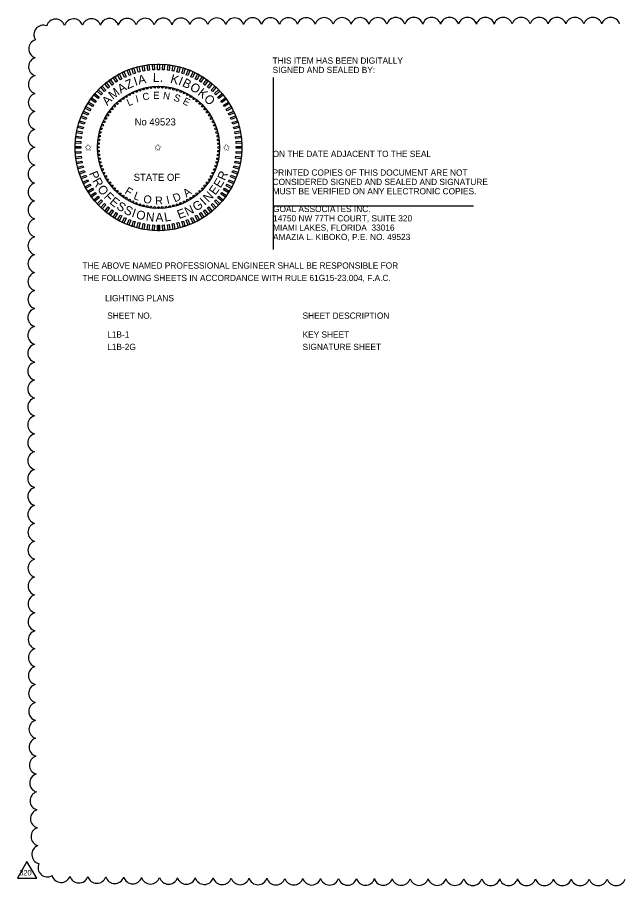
# Model space of a CAD drawing. Extents: x -811.2 to -755.6, y -2295.2 to -2235.1.
# Drawn here: x -783.8 to -777.02, y -2269.67 to -2259.9 of the extents above; entities that cross this region are included whole.
import ezdxf

# ---------------------------------------------------------------- set-up
doc = ezdxf.new("R2010")
doc.units = 0
for name, color, linetype in [('Cloud_dp', 7, 'Continuous'), ('Logo_dp', 7, 'Continuous'), ('NonPlottingEle_dp', 7, 'Continuous'), ('ScratchEle_dp', 7, 'Continuous'), ('TextMisc', 7, 'Continuous'), ('TextNotes', 7, 'Continuous')]:
    doc.layers.add(name, color=color, linetype=linetype)

msp = doc.modelspace()

# ---------------------------------------------------------------- linework, layer by layer
at = {"layer": 'Cloud_dp'}
msp.add_lwpolyline([(-783.6889, -2269.3954), (-783.7966, -2269.5835), (-783.576, -2269.5835)], close=True, dxfattribs=at)
for centre, start, end in [((-782.5594, -2260.0139), 17.87787, 162.87787), ((-782.3579, -2260.0127), 17.82689, 162.82689), ((-782.1564, -2260.0116), 17.78716, 162.78716), ((-781.9548, -2260.0107), 17.75505, 162.75505), ((-781.7533, -2260.0098), 17.72841, 162.72841), ((-781.5518, -2260.009), 17.70584, 162.70584), ((-781.3502, -2260.0084), 17.6864, 162.6864), ((-781.1487, -2260.0077), 17.66942, 162.66942), ((-780.9472, -2260.0072), 17.65443, 162.65443), ((-780.7456, -2260.0066), 17.64106, 162.64106), ((-780.5441, -2260.0062), 17.62905, 162.62905), ((-780.3425, -2260.0057), 17.61817, 162.61817), ((-780.141, -2260.0053), 17.60826, 162.60826), ((-779.9394, -2260.005), 17.59919, 162.59919), ((-779.7379, -2260.0046), 17.59084, 162.59084), ((-779.5364, -2260.0043), 17.58312, 162.58312), ((-779.3348, -2260.004), 17.57595, 162.57595), ((-779.1333, -2260.0038), 17.56928, 162.56928), ((-778.9317, -2260.0036), 17.56305, 162.56305), ((-778.7302, -2260.0033), 17.55721, 162.55721), ((-778.5286, -2260.0032), 17.55172, 162.55172), ((-778.3271, -2260.003), 17.54655, 162.54655), ((-778.1255, -2260.0028), 17.54167, 162.54167), ((-777.924, -2260.0027), 17.53705, 162.53705), ((-777.7224, -2260.0026), 17.53267, 162.53267), ((-777.5209, -2260.0025), 17.52851, 162.52851), ((-777.3194, -2260.0024), 17.52455, 162.52455), ((-777.1178, -2260.0023), 17.52079, 162.52079), ((-783.5053, -2260.0909), 68.43954, 213.43954), ((-783.3652, -2260.0225), 18.59454, 163.59454), ((-783.1638, -2260.0193), 18.21421, 163.21421), ((-782.9624, -2260.0171), 18.04696, 163.04696), ((-782.7609, -2260.0154), 17.94666, 162.94666), ((-783.563, -2260.2503), 106.80445, 251.80445), ((-783.565, -2260.4517), 107.04367, 252.04367), ((-783.5664, -2260.6532), 107.15618, 252.15618), ((-783.5675, -2260.8547), 107.22533, 252.22533), ((-783.5684, -2261.0562), 107.27338, 252.27338), ((-783.5691, -2261.2578), 107.30928, 252.30928), ((-783.5697, -2261.4593), 107.33743, 252.33743), ((-783.5703, -2261.6608), 107.36027, 252.36027), ((-783.5707, -2261.8624), 107.37928, 252.37928), ((-783.5711, -2262.0639), 107.39543, 252.39543), ((-783.5715, -2262.2655), 107.40937, 252.40937), ((-783.5717, -2262.467), 107.42156, 252.42156), ((-783.572, -2262.6685), 107.43234, 252.43234), ((-783.5722, -2262.8701), 107.44197, 252.44197), ((-783.5724, -2263.0716), 107.45063, 252.45063), ((-783.5726, -2263.2732), 107.45847, 252.45847), ((-783.5727, -2263.4747), 107.46563, 252.46563), ((-783.5728, -2263.6763), 107.47218, 252.47218), ((-783.5729, -2263.8778), 107.47822, 252.47822), ((-783.573, -2264.0794), 107.4838, 252.4838), ((-783.573, -2264.2809), 107.48899, 252.48899), ((-783.5731, -2264.4824), 107.49382, 252.49382), ((-783.5731, -2264.684), 107.49843, 252.49843), ((-783.573, -2264.8855), 107.51148, 252.51148), ((-783.573, -2265.0871), 107.53101, 252.53101), ((-783.5728, -2265.2886), 107.55191, 252.55191), ((-783.5726, -2265.4901), 107.57435, 252.57435), ((-783.5723, -2265.6917), 107.59852, 252.59852), ((-783.5719, -2265.8932), 107.62468, 252.62468), ((-783.5714, -2266.0947), 107.65309, 252.65309), ((-783.5708, -2266.2963), 107.68411, 252.68411), ((-783.5701, -2266.4978), 107.71817, 252.71817), ((-783.5693, -2266.6993), 107.75578, 252.75578), ((-783.5683, -2266.9009), 107.79762, 252.79762), ((-783.5672, -2267.1024), 107.84454, 252.84454), ((-783.5659, -2267.3039), 107.89767, 252.89767), ((-783.5644, -2267.5054), 107.95851, 252.95851), ((-783.5626, -2267.7069), 108.02912, 253.02912), ((-783.5606, -2267.9084), 108.11243, 253.11243), ((-783.5583, -2268.1099), 108.21279, 253.21279), ((-783.5556, -2268.3113), 108.33694, 253.33694), ((-783.5523, -2268.5128), 108.49611, 253.49611), ((-783.5485, -2268.7142), 108.71068, 253.71068), ((-783.5437, -2268.9155), 109.02298, 254.02298), ((-783.5374, -2269.1166), 109.54201, 254.54201), ((-783.5282, -2269.3173), 110.71007, 255.71007), ((-783.4585, -2269.4643), 155.06518, 300.06518), ((-783.3038, -2269.5272), 195.62937, 340.62937), ((-783.1027, -2269.5327), 196.26473, 341.26473), ((-782.9013, -2269.5365), 196.54985, 341.54985), ((-782.6999, -2269.5396), 196.72204, 341.72204), ((-782.4984, -2269.5421), 196.84059, 341.84059), ((-782.2969, -2269.5443), 196.92865, 341.92865), ((-782.0954, -2269.5461), 196.99739, 341.99739), ((-781.8939, -2269.5478), 197.053, 342.053), ((-781.6924, -2269.5493), 197.09919, 342.09919), ((-781.4909, -2269.5506), 197.13834, 342.13834), ((-781.2893, -2269.5519), 197.17209, 342.17209), ((-781.0878, -2269.553), 197.20158, 342.20158), ((-780.8863, -2269.554), 197.22762, 342.22762), ((-780.6847, -2269.5549), 197.25085, 342.25085), ((-780.4832, -2269.5557), 197.27174, 342.27174), ((-780.2817, -2269.5565), 197.29065, 342.29065), ((-780.0801, -2269.5572), 197.30788, 342.30788), ((-779.8786, -2269.5578), 197.32367, 342.32367), ((-779.6771, -2269.5584), 197.3382, 342.3382), ((-779.4755, -2269.559), 197.35163, 342.35163), ((-779.274, -2269.5595), 197.3641, 342.3641), ((-779.0724, -2269.5599), 197.37571, 342.37571), ((-778.8709, -2269.5604), 197.38657, 342.38657), ((-778.6693, -2269.5607), 197.39674, 342.39674), ((-778.4678, -2269.5611), 197.40629, 342.40629), ((-778.2663, -2269.5614), 197.4153, 342.4153), ((-778.0647, -2269.5617), 197.4238, 342.4238), ((-777.8632, -2269.5619), 197.43184, 342.43184), ((-777.6616, -2269.5622), 197.43947, 342.43947), ((-777.4601, -2269.5624), 197.44671, 342.44671), ((-777.2585, -2269.5625), 197.4536, 342.4536), ((-777.057, -2269.5627), 197.46017, 342.46017)]:
    msp.add_arc(centre, 0.1057, start, end, dxfattribs=at)
at = {"layer": 'Logo_dp'}
for p, q in [((-782.2178, -2262.2978), (-782.218, -2262.2353)), ((-782.2078, -2262.2978), (-782.208, -2262.2353)), ((-782.1978, -2262.2978), (-782.198, -2262.2353))]:
    msp.add_line(p, q, dxfattribs=at)
for points in [[(-782.5205, -2260.543), (-782.5392, -2260.5504), (-782.5622, -2260.4923), (-782.5434, -2260.4849)], [(-782.4685, -2260.525), (-782.4877, -2260.5312), (-782.507, -2260.4718), (-782.4878, -2260.4656)], [(-782.4156, -2260.5102), (-782.4351, -2260.5152), (-782.4506, -2260.4548), (-782.4311, -2260.4498)], [(-782.3618, -2260.4989), (-782.3816, -2260.5026), (-782.3933, -2260.4413), (-782.3735, -2260.4375)], [(-782.3074, -2260.4909), (-782.3274, -2260.4934), (-782.3352, -2260.4315), (-782.3152, -2260.4289)], [(-782.2526, -2260.4864), (-782.2727, -2260.4876), (-782.2767, -2260.4253), (-782.2565, -2260.424)], [(-782.1976, -2260.4853), (-782.2178, -2260.4853), (-782.2178, -2260.4228), (-782.1976, -2260.4228)], [(-782.1427, -2260.4876), (-782.1629, -2260.4864), (-782.1589, -2260.4241), (-782.1388, -2260.4253)], [(-782.088, -2260.4934), (-782.1081, -2260.4909), (-782.1002, -2260.429), (-782.0802, -2260.4315)], [(-782.0338, -2260.5027), (-782.0537, -2260.4989), (-782.042, -2260.4376), (-782.0221, -2260.4413)], [(-781.9803, -2260.5153), (-781.9999, -2260.5103), (-781.9844, -2260.4498), (-781.9648, -2260.4548)], [(-781.9277, -2260.5312), (-781.9469, -2260.525), (-781.9276, -2260.4656), (-781.9084, -2260.4719)], [(-781.8762, -2260.5505), (-781.895, -2260.543), (-781.872, -2260.485), (-781.8532, -2260.4924)], [(-782.6681, -2260.616), (-782.6851, -2260.6268), (-782.7186, -2260.5741), (-782.7015, -2260.5633)], [(-782.6204, -2260.5886), (-782.6381, -2260.5983), (-782.6682, -2260.5436), (-782.6505, -2260.5339)], [(-782.5712, -2260.5642), (-782.5894, -2260.5728), (-782.616, -2260.5163), (-782.5978, -2260.5077)], [(-781.826, -2260.5729), (-781.8443, -2260.5643), (-781.8177, -2260.5078), (-781.7994, -2260.5164)], [(-781.7773, -2260.5984), (-781.795, -2260.5887), (-781.7649, -2260.534), (-781.7473, -2260.5437)], [(-781.7303, -2260.6269), (-781.7474, -2260.6161), (-781.7139, -2260.5634), (-781.6969, -2260.5742)], [(-782.7994, -2260.7155), (-782.8141, -2260.7293), (-782.8568, -2260.6838), (-782.8421, -2260.6699)], [(-782.7577, -2260.6796), (-782.7733, -2260.6925), (-782.8131, -2260.6443), (-782.7975, -2260.6315)], [(-782.7139, -2260.6464), (-782.7302, -2260.6583), (-782.7669, -2260.6078), (-782.7506, -2260.5959)], [(-781.6852, -2260.6584), (-781.7016, -2260.6465), (-781.6649, -2260.596), (-781.6485, -2260.6079)], [(-781.6422, -2260.6926), (-781.6578, -2260.6797), (-781.618, -2260.6316), (-781.6024, -2260.6445)], [(-781.6014, -2260.7294), (-781.6161, -2260.7156), (-781.5734, -2260.6701), (-781.5586, -2260.6839)], [(-782.8755, -2260.7947), (-782.8884, -2260.8102), (-782.9365, -2260.7704), (-782.9237, -2260.7549)], [(-782.8387, -2260.7539), (-782.8525, -2260.7686), (-782.898, -2260.7258), (-782.8842, -2260.7111)], [(-781.563, -2260.7687), (-781.5768, -2260.754), (-781.5313, -2260.7113), (-781.5175, -2260.726)], [(-781.5271, -2260.8104), (-781.54, -2260.7948), (-781.4919, -2260.755), (-781.479, -2260.7706)], [(-782.9412, -2260.8828), (-782.952, -2260.8999), (-783.0047, -2260.8664), (-782.9939, -2260.8494)], [(-782.9097, -2260.8377), (-782.9216, -2260.8541), (-782.9721, -2260.8174), (-782.9603, -2260.801)], [(-781.4939, -2260.8542), (-781.5058, -2260.8379), (-781.4553, -2260.8012), (-781.4434, -2260.8175)], [(-781.4635, -2260.9), (-781.4744, -2260.883), (-781.4216, -2260.8495), (-781.4108, -2260.8666)], [(-782.9952, -2260.9785), (-783.0038, -2260.9968), (-783.0603, -2260.9702), (-783.0517, -2260.9519)], [(-782.9697, -2260.9298), (-782.9794, -2260.9475), (-783.0341, -2260.9174), (-783.0244, -2260.8997)], [(-781.4361, -2260.9477), (-781.4458, -2260.93), (-781.3911, -2260.8999), (-781.3814, -2260.9176)], [(-781.4117, -2260.9969), (-781.4203, -2260.9787), (-781.3638, -2260.9521), (-781.3552, -2260.9704)], [(-783.0369, -2261.0802), (-783.0431, -2261.0994), (-783.1025, -2261.0801), (-783.0963, -2261.0609)], [(-783.0176, -2261.0287), (-783.0251, -2261.0475), (-783.0831, -2261.0245), (-783.0757, -2261.0057)], [(-781.3905, -2261.0477), (-781.3979, -2261.0289), (-781.3399, -2261.0059), (-781.3324, -2261.0247)], [(-781.3725, -2261.0996), (-781.3787, -2261.0804), (-781.3193, -2261.0611), (-781.3131, -2261.0803)], [(-783.0654, -2261.1863), (-783.0692, -2261.2062), (-783.1306, -2261.1945), (-783.1268, -2261.1746)], [(-783.0528, -2261.1328), (-783.0578, -2261.1524), (-783.1183, -2261.1368), (-783.1133, -2261.1173)], [(-781.3577, -2261.1526), (-781.3628, -2261.133), (-781.3023, -2261.1175), (-781.2973, -2261.137)], [(-781.3464, -2261.2063), (-781.3502, -2261.1865), (-781.2888, -2261.1748), (-781.285, -2261.1946)], [(-783.0747, -2261.2405), (-783.0772, -2261.2606), (-783.1391, -2261.2527), (-783.1366, -2261.2327)], [(-781.3384, -2261.2607), (-781.3409, -2261.2407), (-781.279, -2261.2329), (-781.2765, -2261.2529)], [(-783.0828, -2261.3501), (-783.0828, -2261.3703), (-783.1453, -2261.3703), (-783.1453, -2261.3501)], [(-783.0805, -2261.2952), (-783.0817, -2261.3153), (-783.1441, -2261.3114), (-783.1428, -2261.2913)], [(-781.3339, -2261.3155), (-781.3351, -2261.2954), (-781.2728, -2261.2915), (-781.2716, -2261.3116)], [(-781.3328, -2261.3705), (-781.3328, -2261.3503), (-781.2703, -2261.3503), (-781.2703, -2261.3705)], [(-783.0818, -2261.4051), (-783.0805, -2261.4252), (-783.1428, -2261.4291), (-783.1441, -2261.409)], [(-783.0772, -2261.4599), (-783.0747, -2261.4799), (-783.1366, -2261.4877), (-783.1392, -2261.4677)], [(-781.341, -2261.4801), (-781.3384, -2261.4601), (-781.2765, -2261.4679), (-781.279, -2261.4879)], [(-781.3351, -2261.4254), (-781.3339, -2261.4053), (-781.2716, -2261.4092), (-781.2728, -2261.4293)], [(-783.0693, -2261.5143), (-783.0655, -2261.5341), (-783.1268, -2261.5458), (-783.1306, -2261.526)], [(-783.0579, -2261.568), (-783.0529, -2261.5876), (-783.1133, -2261.6031), (-783.1184, -2261.5836)], [(-781.3628, -2261.5878), (-781.3578, -2261.5682), (-781.2973, -2261.5838), (-781.3023, -2261.6033)], [(-781.3502, -2261.5343), (-781.3464, -2261.5144), (-781.2851, -2261.5261), (-781.2889, -2261.546)], [(-783.0432, -2261.621), (-783.0369, -2261.6402), (-783.0963, -2261.6595), (-783.1025, -2261.6403)], [(-781.3788, -2261.6404), (-781.3725, -2261.6212), (-781.3131, -2261.6405), (-781.3194, -2261.6597)], [(-783.0251, -2261.673), (-783.0177, -2261.6917), (-783.0758, -2261.7147), (-783.0832, -2261.6959)], [(-783.0039, -2261.7237), (-782.9953, -2261.7419), (-783.0518, -2261.7685), (-783.0604, -2261.7502)], [(-781.4204, -2261.7421), (-781.4118, -2261.7238), (-781.3553, -2261.7504), (-781.3639, -2261.7687)], [(-781.398, -2261.6919), (-781.3906, -2261.6731), (-781.3325, -2261.6961), (-781.3399, -2261.7149)], [(-782.9795, -2261.7729), (-782.9698, -2261.7906), (-783.0245, -2261.8207), (-783.0342, -2261.803)], [(-782.9521, -2261.8206), (-782.9413, -2261.8376), (-782.994, -2261.8711), (-783.0048, -2261.854)], [(-781.4745, -2261.8378), (-781.4636, -2261.8207), (-781.4109, -2261.8542), (-781.4217, -2261.8712)], [(-781.4459, -2261.7908), (-781.4362, -2261.7731), (-781.3815, -2261.8032), (-781.3912, -2261.8209)], [(-782.9217, -2261.8664), (-782.9099, -2261.8827), (-782.9604, -2261.9194), (-782.9722, -2261.9031)], [(-782.8885, -2261.9102), (-782.8757, -2261.9258), (-782.9238, -2261.9656), (-782.9366, -2261.95)], [(-782.8527, -2261.9519), (-782.8388, -2261.9666), (-782.8844, -2262.0093), (-782.8982, -2261.9946)], [(-781.5769, -2261.9667), (-781.5631, -2261.952), (-781.5176, -2261.9948), (-781.5314, -2262.0095)], [(-781.5401, -2261.9259), (-781.5272, -2261.9104), (-781.4791, -2261.9502), (-781.492, -2261.9657)], [(-781.5059, -2261.8829), (-781.494, -2261.8665), (-781.4435, -2261.9032), (-781.4554, -2261.9196)], [(-782.8142, -2261.9912), (-782.7995, -2262.005), (-782.8423, -2262.0505), (-782.857, -2262.0367)], [(-782.7734, -2262.028), (-782.7579, -2262.0409), (-782.7977, -2262.089), (-782.8132, -2262.0761)], [(-781.6579, -2262.041), (-781.6423, -2262.0281), (-781.6025, -2262.0763), (-781.6181, -2262.0891)], [(-781.6162, -2262.0051), (-781.6015, -2261.9913), (-781.5588, -2262.0368), (-781.5735, -2262.0507)], [(-782.7304, -2262.0622), (-782.7141, -2262.0741), (-782.7508, -2262.1246), (-782.7671, -2262.1127)], [(-782.6853, -2262.0937), (-782.6682, -2262.1045), (-782.7017, -2262.1572), (-782.7187, -2262.1464)], [(-782.6383, -2262.1222), (-782.6206, -2262.1319), (-782.6507, -2262.1866), (-782.6684, -2262.1769)], [(-782.5896, -2262.1477), (-782.5713, -2262.1563), (-782.5979, -2262.2128), (-782.6162, -2262.2042)], [(-781.8445, -2262.1564), (-781.8262, -2262.1478), (-781.7996, -2262.2043), (-781.8179, -2262.2129)], [(-781.7952, -2262.132), (-781.7775, -2262.1223), (-781.7474, -2262.177), (-781.7651, -2262.1867)], [(-781.7475, -2262.1046), (-781.7305, -2262.0938), (-781.697, -2262.1465), (-781.7141, -2262.1573)], [(-781.7017, -2262.0742), (-781.6854, -2262.0623), (-781.6487, -2262.1129), (-781.665, -2262.1247)], [(-782.5394, -2262.1701), (-782.5206, -2262.1776), (-782.5436, -2262.2356), (-782.5624, -2262.2282)], [(-782.4879, -2262.1894), (-782.4687, -2262.1956), (-782.488, -2262.255), (-782.5072, -2262.2487)], [(-782.4353, -2262.2053), (-782.4157, -2262.2103), (-782.4313, -2262.2708), (-782.4508, -2262.2658)], [(-782.3818, -2262.2179), (-782.362, -2262.2217), (-782.3737, -2262.283), (-782.3935, -2262.2793)], [(-782.3276, -2262.2272), (-782.3076, -2262.2297), (-782.3154, -2262.2916), (-782.3354, -2262.2891)], [(-782.2729, -2262.233), (-782.2528, -2262.2342), (-782.2567, -2262.2966), (-782.2768, -2262.2953)], [(-782.218, -2262.2353), (-782.1978, -2262.2353), (-782.1978, -2262.2978), (-782.218, -2262.2978)], [(-782.163, -2262.2342), (-782.1429, -2262.233), (-782.139, -2262.2953), (-782.1591, -2262.2966)], [(-782.1082, -2262.2297), (-782.0882, -2262.2272), (-782.0804, -2262.2891), (-782.1004, -2262.2917)], [(-782.0539, -2262.2217), (-782.034, -2262.218), (-782.0223, -2262.2793), (-782.0422, -2262.2831)], [(-782.0001, -2262.2104), (-781.9805, -2262.2054), (-781.965, -2262.2658), (-781.9845, -2262.2709)], [(-781.9471, -2262.1957), (-781.9279, -2262.1894), (-781.9086, -2262.2488), (-781.9278, -2262.255)], [(-781.8952, -2262.1776), (-781.8764, -2262.1702), (-781.8534, -2262.2283), (-781.8722, -2262.2357)]]:
    msp.add_lwpolyline(points, close=True, dxfattribs=at)
for centre in [(-782.3342, -2260.6947), (-782.2922, -2260.6881), (-782.2498, -2260.6841), (-782.2072, -2260.6828), (-782.1647, -2260.6842), (-782.1223, -2260.6882), (-782.0803, -2260.6949), (-782.5703, -2260.788), (-782.5337, -2260.7664), (-782.4958, -2260.7471), (-782.4567, -2260.7302), (-782.4166, -2260.7158), (-782.3757, -2260.704), (-782.0388, -2260.7043), (-781.9979, -2260.7162), (-781.9579, -2260.7306), (-781.9189, -2260.7476), (-781.8809, -2260.7669), (-781.8443, -2260.7886), (-782.7013, -2260.8961), (-782.6712, -2260.8661), (-782.6392, -2260.8379), (-782.6056, -2260.8119), (-781.8092, -2260.8125), (-781.7755, -2260.8387), (-781.7436, -2260.8668), (-782.7556, -2260.9616), (-782.7295, -2260.928), (-781.7136, -2260.897), (-781.6855, -2260.9289), (-781.6594, -2260.9626), (-782.8206, -2261.0713), (-782.8012, -2261.0334), (-782.7795, -2260.9968), (-781.6355, -2260.9978), (-781.6139, -2261.0344), (-781.5946, -2261.0724), (-782.852, -2261.1504), (-782.8375, -2261.1104), (-781.5777, -2261.1114), (-781.5633, -2261.1515), (-782.8799, -2261.2748), (-782.8732, -2261.2328), (-782.8639, -2261.1913), (-781.5515, -2261.1924), (-781.5422, -2261.2339), (-781.5356, -2261.276), (-782.8853, -2261.3597), (-782.8839, -2261.3172), (-781.5316, -2261.3183), (-781.5303, -2261.3609), (-782.884, -2261.4023), (-782.88, -2261.4447), (-781.5358, -2261.4458), (-781.5317, -2261.4034), (-782.8734, -2261.4867), (-782.8641, -2261.5282), (-782.8523, -2261.5691), (-781.5637, -2261.5702), (-781.5518, -2261.5293), (-781.5425, -2261.4878), (-782.8379, -2261.6092), (-782.821, -2261.6482), (-781.5951, -2261.6493), (-781.5781, -2261.6102), (-782.8018, -2261.6862), (-782.7801, -2261.7228), (-782.7562, -2261.7581), (-781.6601, -2261.759), (-781.6361, -2261.7238), (-781.6144, -2261.6872), (-782.7302, -2261.7917), (-782.7021, -2261.8236), (-782.672, -2261.8538), (-781.7445, -2261.8545), (-781.7143, -2261.8245), (-781.6862, -2261.7926), (-782.6401, -2261.8819), (-782.6065, -2261.9081), (-782.5713, -2261.932), (-782.5347, -2261.9537), (-781.8819, -2261.9542), (-781.8453, -2261.9326), (-781.8101, -2261.9087), (-781.7764, -2261.8827), (-782.4968, -2261.9731), (-782.4577, -2261.99), (-782.4177, -2262.0044), (-782.3768, -2262.0163), (-782.3353, -2262.0257), (-782.2933, -2262.0324), (-782.2509, -2262.0364), (-782.2078, -2262.0378), (-782.1658, -2262.0365), (-782.1235, -2262.0325), (-782.0814, -2262.0259), (-782.0399, -2262.0166), (-781.999, -2262.0048), (-781.9589, -2261.9904), (-781.9199, -2261.9735)]:
    msp.add_circle(centre, 0.01, dxfattribs=at)
at = {"layer": 'NonPlottingEle_dp'}
for radius in [0.9375, 0.6875]:
    msp.add_circle((-782.2078, -2261.3603), radius, dxfattribs=at)
at = {"layer": 'ScratchEle_dp'}
for p, q in [((-780.9186, -2260.5734), (-780.9186, -2262.5081)), ((-780.9186, -2262.0181), (-778.6618, -2262.0181))]:
    msp.add_line(p, q, dxfattribs=at)

# ---------------------------------------------------------------- texts
at = {"layer": 'Cloud_dp'}
msp.add_text('320', height=0.05998, rotation=0, dxfattribs=at).set_placement((-783.7746, -2269.5534))
at = {"layer": 'Logo_dp'}
for s, rotation, p in [('I', 14.81888, (-782.4534, -2260.8551)), ('C', 8.98261, (-782.3808, -2260.8324)), ('E', 359.96623, (-782.2681, -2260.8135)), ('N', 350.64643, (-782.1612, -2260.8121)), ('S', 341.03996, (-782.0441, -2260.8309)), ('L', 23.30524, (-782.544, -2260.898)), ('E', 331.16864, (-781.9426, -2260.8635))]:
    msp.add_text(s, height=0.08, rotation=rotation, dxfattribs=at).set_placement(p)
for p in [(-783.0428, -2261.3983), (-782.2581, -2261.3983), (-781.4862, -2261.3983)]:
    msp.add_text('✩', height=0.08, dxfattribs=at).set_placement(p)
at = {"layer": 'TextMisc'}
for s, height, p in [('THIS ITEM HAS BEEN DIGITALLY', 0.07, (-780.9235, -2260.4183)), ('SIGNED AND SEALED BY:', 0.07, (-780.9235, -2260.5233)), ('No 49523', 0.08, (-782.4768, -2261.1131)), ('ON THE DATE ADJACENT TO THE SEAL', 0.07, (-780.9235, -2261.4683)), ('STATE OF', 0.08, (-782.4875, -2261.7365)), ('PRINTED COPIES OF THIS DOCUMENT ARE NOT ', 0.07, (-780.9235, -2261.6783)), ('CONSIDERED SIGNED AND SEALED AND SIGNATURE ', 0.07, (-780.9235, -2261.7833)), ('MUST BE VERIFIED ON ANY ELECTRONIC COPIES.', 0.07, (-780.9235, -2261.8883)), ('GOAL ASSOCIATES INC.', 0.07, (-780.9186, -2262.0881)), ('14750 NW 77TH COURT, SUITE 320', 0.07, (-780.9186, -2262.1931)), ('MIAMI LAKES, FLORIDA  33016', 0.07, (-780.9186, -2262.2981)), ('AMAZIA L. KIBOKO, P.E. NO. 49523', 0.07, (-780.9186, -2262.4031)), ('THE ABOVE NAMED PROFESSIONAL ENGINEER SHALL BE RESPONSIBLE FOR ', 0.07, (-783.0626, -2262.7243)), ('THE FOLLOWING SHEETS IN ACCORDANCE WITH RULE 61G15-23.004, F.A.C.', 0.07, (-783.0626, -2262.8643)), ('LIGHTING PLANS', 0.07, (-782.8089, -2263.0913))]:
    msp.add_text(s, height=height, dxfattribs=at).set_placement(p)
for s, height, rotation, p in [('Z', 0.1, 23.30524, (-782.5548, -2260.707)), ('I', 0.1, 17.68363, (-782.4679, -2260.6694)), ('A', 0.1, 11.91844, (-782.4286, -2260.6534)), ('L', 0.1, 359.96623, (-782.2714, -2260.623)), ('K', 0.1, 344.27273, (-782.0807, -2260.6302)), ('I', 0.1, 337.77772, (-781.9921, -2260.652)), ('B', 0.1, 334.48695, (-781.9482, -2260.6673)), ('M', 0.1, 39.30005, (-782.7212, -2260.8277)), ('A', 0.1, 31.46601, (-782.6322, -2260.7556)), ('.', 0.1, 353.78581, (-782.1947, -2260.6201)), ('O', 0.1, 327.82385, (-781.8635, -2260.7059)), ('K', 0.1, 321.0594, (-781.7739, -2260.7631)), ('O', 0.1, 314.20329, (-781.7043, -2260.8207)), ('A', 0.1, 46.80938, (-782.7835, -2260.8962)), ('P', 0.1, 293.19548, (-782.9935, -2261.6519)), ('R', 0.1, 65.28865, (-781.4614, -2261.7412)), ('R', 0.1, 300.25949, (-782.9566, -2261.7378)), ('E', 0.1, 58.61694, (-781.5106, -2261.8252)), ('O', 0.1, 307.26617, (-782.9025, -2261.8296)), ('F', 0.1, 314.20329, (-782.8291, -2261.9221)), ('F', 0.09, 328.53399, (-782.5962, -2261.8756)), ('L', 0.09, 339.48752, (-782.495, -2261.9386)), ('A', 0.09, 35.54629, (-781.8934, -2261.9249)), ('N', 0.1, 44.34211, (-781.6479, -2261.9838)), ('E', 0.1, 53.99864, (-781.5679, -2261.9039)), ('E', 0.1, 321.0594, (-782.7657, -2261.9857)), ('O', 0.09, 348.08156, (-782.3856, -2261.9792)), ('R', 0.09, 3.10738, (-782.2434, -2262.0054)), ('I', 0.09, 12.52485, (-782.1092, -2261.9963)), ('D', 0.09, 22.22228, (-782.0251, -2261.9794)), ('G', 0.1, 34.11362, (-781.7834, -2262.084)), ('I', 0.1, 41.83906, (-781.6873, -2262.018)), ('S', 0.1, 327.82385, (-782.6895, -2262.0462)), ('S', 0.1, 334.48695, (-782.6064, -2262.0976)), ('I', 0.1, 341.03996, (-782.5178, -2262.1389)), ('E', 0.1, 20.51248, (-781.9761, -2262.1675)), ('N', 0.1, 26.0618, (-781.8846, -2262.1342)), ('O', 0.1, 344.27273, (-782.4687, -2262.1565)), ('N', 0.1, 353.78581, (-782.3543, -2262.1864)), ('A', 0.1, 359.96623, (-782.242, -2262.1974)), ('L', 0.1, 8.98261, (-782.1363, -2262.1966))]:
    msp.add_text(s, height=height, rotation=rotation, dxfattribs=at).set_placement(p)
at = {"layer": 'TextNotes'}
for s, p in [('SHEET NO.', (-782.7855, -2263.2883)), ('SHEET DESCRIPTION', (-780.5865, -2263.2883)), ('L1B-1', (-782.7855, -2263.5005)), ('KEY SHEET', (-780.5865, -2263.5005)), ('L1B-2G', (-782.7855, -2263.6405)), ('SIGNATURE SHEET', (-780.5865, -2263.6405))]:
    msp.add_text(s, height=0.07, dxfattribs=at).set_placement(p)

doc.saveas('drawing.dxf')
